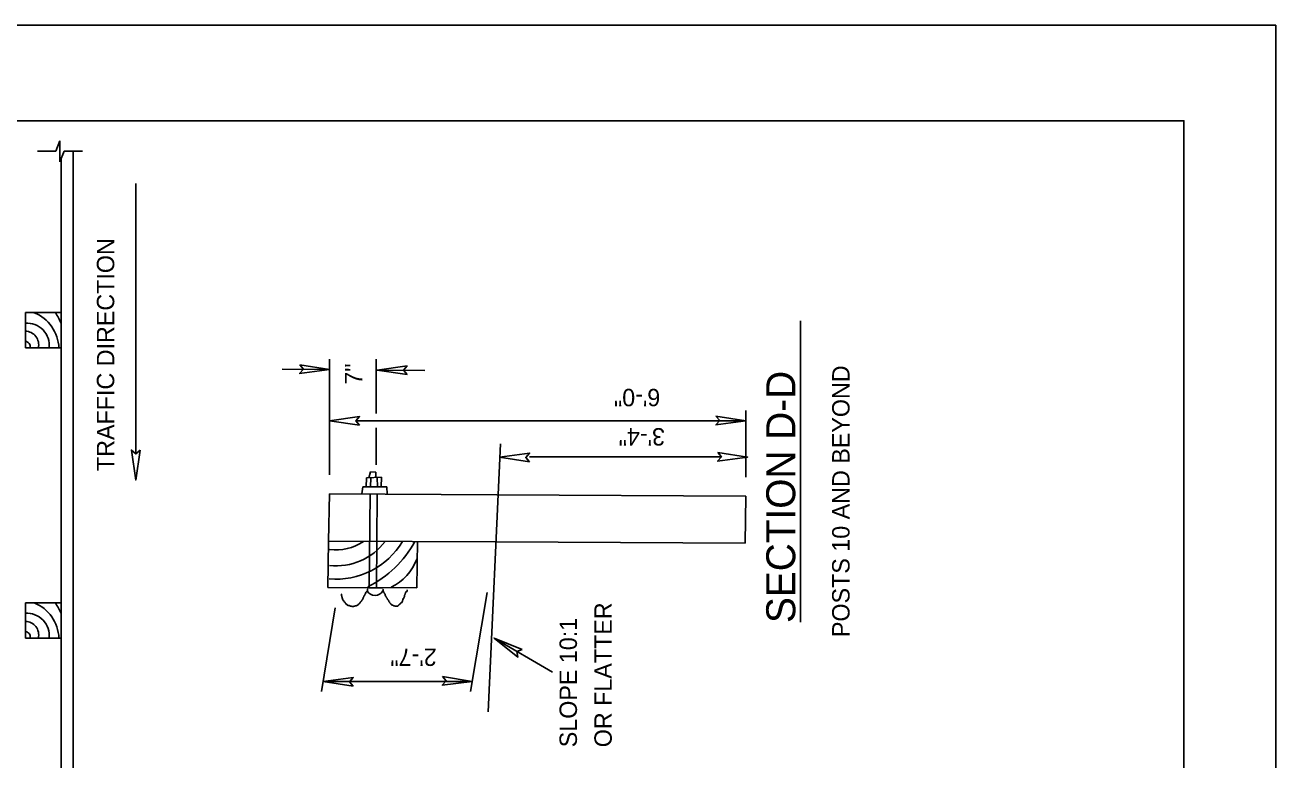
# Model space of a CAD drawing. Extents: x 12.2 to 54.5, y -7.8 to 16.1.
# Drawn here: x 50.224 to 54.534, y 0.687 to 3.22 of the extents above; entities that cross this region are included whole.
import ezdxf

# ---------------------------------------------------------------- set-up
doc = ezdxf.new("R2010")
doc.units = 0
for name, color, linetype in [('BORD-LINE', 7, 'Continuous'), ('DETL-DIMS', 7, 'Continuous'), ('DETL-LINE', 7, 'Continuous'), ('DETL-NOTE', 7, 'Continuous'), ('DETL-PATT', 7, 'Continuous'), ('DETL-TITL', 7, 'Continuous'), ('USER-BORD', 7, 'Continuous')]:
    doc.layers.add(name, color=color, linetype=linetype)

msp = doc.modelspace()

# ---------------------------------------------------------------- linework, layer by layer
at = {"layer": 'BORD-LINE'}
msp.add_lwpolyline([(46.8431, 2.8902), (54.2173, 2.8902), (54.2173, -7.4629), (46.8431, -7.4629)], close=True, dxfattribs=at)
at = {"layer": 'DETL-DIMS'}
for p, q in [((50.6056, 1.7422), (50.6056, 2.6735)), ((51.1095, 2.0345), (51.2734, 2.0332)), ((51.1699, 2.019), (51.183, 2.0339)), ((51.1699, 2.019), (51.2734, 2.0332)), ((51.1702, 2.0491), (51.2734, 2.0332)), ((51.1702, 2.0491), (51.183, 2.0339)), ((51.2734, 1.6698), (51.2734, 2.0682)), ((51.4335, 1.8814), (51.4335, 2.0682)), ((51.5405, 2.0455), (51.4371, 2.0312)), ((51.4371, 2.0312), (51.601, 2.03)), ((51.5402, 2.0154), (51.4371, 2.0312)), ((51.5405, 2.0455), (51.5275, 2.0305)), ((51.5402, 2.0154), (51.5275, 2.0305)), ((51.3768, 1.8706), (51.2734, 1.8564)), ((51.3765, 1.8405), (51.2734, 1.8564)), ((51.3768, 1.8706), (51.3638, 1.8556)), ((52.7079, 1.8564), (51.3638, 1.8556)), ((51.3765, 1.8405), (51.3638, 1.8556)), ((52.6045, 1.842), (52.6176, 1.857)), ((52.6045, 1.842), (52.7079, 1.8564)), ((52.6047, 1.8721), (52.7079, 1.8564)), ((52.6047, 1.8721), (52.6176, 1.857)), ((52.708, 1.8914), (52.7075, 1.6615)), ((51.4335, 1.7049), (51.4335, 1.8314)), ((50.5905, 1.7551), (50.6056, 1.6518)), ((50.5905, 1.7551), (50.6056, 1.7422)), ((50.6207, 1.7551), (50.6056, 1.6518)), ((50.6207, 1.7551), (50.6056, 1.7422)), ((51.9624, 1.7446), (51.859, 1.7308)), ((51.9621, 1.7145), (51.859, 1.7308)), ((51.9624, 1.7446), (51.9493, 1.7297)), ((51.9621, 1.7145), (51.9493, 1.7297)), ((52.6232, 1.7319), (51.9622, 1.7325)), ((52.6102, 1.7169), (52.6232, 1.7319)), ((52.6102, 1.7169), (52.7137, 1.7308)), ((52.6105, 1.7471), (52.7137, 1.7308)), ((52.6105, 1.7471), (52.6232, 1.7319)), ((51.8163, 1.2645), (51.7592, 0.9235)), ((51.2927, 1.212), (51.2456, 0.9234)), ((51.922, 1.0419), (51.8403, 1.107)), ((51.9371, 1.0679), (51.8403, 1.107)), ((52.0409, 0.9899), (51.8403, 1.107)), ((51.9371, 1.0679), (51.9184, 1.0614)), ((51.922, 1.0419), (51.9184, 1.0614)), ((51.3547, 0.9713), (51.2512, 0.958)), ((51.3542, 0.9412), (51.2512, 0.958)), ((51.765, 0.958), (51.2512, 0.958)), ((51.3547, 0.9713), (51.3415, 0.9565)), ((51.3542, 0.9412), (51.3415, 0.9565)), ((51.6616, 0.9447), (51.6747, 0.9595)), ((51.6616, 0.9447), (51.765, 0.958)), ((51.662, 0.9748), (51.765, 0.958)), ((51.662, 0.9748), (51.6747, 0.9595))]:
    msp.add_line(p, q, dxfattribs=at)
for points in [[(51.1702, 2.0491), (51.2734, 2.0332), (51.1699, 2.019), (51.183, 2.0339)], [(51.5402, 2.0154), (51.4371, 2.0312), (51.5405, 2.0455), (51.5275, 2.0305)], [(51.3765, 1.8405), (51.2734, 1.8564), (51.3768, 1.8706), (51.3638, 1.8556)], [(52.6047, 1.8721), (52.7079, 1.8564), (52.6045, 1.842), (52.6176, 1.857)], [(50.6207, 1.7551), (50.6056, 1.6518), (50.5905, 1.7551), (50.6056, 1.7422)], [(51.9621, 1.7145), (51.859, 1.7308), (51.9624, 1.7446), (51.9493, 1.7297)], [(52.6105, 1.7471), (52.7137, 1.7308), (52.6102, 1.7169), (52.6232, 1.7319)], [(51.9371, 1.0679), (51.8403, 1.107), (51.922, 1.0419), (51.9184, 1.0614)], [(51.3542, 0.9412), (51.2512, 0.958), (51.3547, 0.9713), (51.3415, 0.9565)], [(51.662, 0.9748), (51.765, 0.958), (51.6616, 0.9447), (51.6747, 0.9595)]]:
    msp.add_lwpolyline(points, close=True, dxfattribs=at)
at = {"layer": 'DETL-LINE'}
for p, q in [((50.3296, 2.7851), (50.3441, 2.821)), ((50.3441, 2.821), (50.3441, 2.7492)), ((50.2663, 2.7851), (50.3235, 2.7851)), ((50.3296, 2.7851), (50.3235, 2.7851)), ((50.3441, 2.7492), (50.3586, 2.7851)), ((50.3485, -5.332), (50.3485, 2.7601)), ((50.3647, 2.7851), (50.3586, 2.7851)), ((50.3647, 2.7851), (50.4219, 2.7851)), ((50.3897, 2.7851), (50.3836, 2.7851)), ((50.3897, -5.332), (50.3897, 2.7851)), ((50.225, 2.1071), (50.225, 2.229)), ((50.225, 2.229), (50.3485, 2.229)), ((50.3485, 2.1071), (50.3485, 2.229)), ((50.3485, 2.168), (50.3485, 2.168)), ((50.3485, 2.168), (50.3485, 2.168)), ((50.225, 2.1071), (50.3485, 2.1071)), ((51.8616, 1.7768), (51.8195, 0.8528)), ((51.3991, 1.6289), (51.4, 1.6592)), ((51.4, 1.6592), (51.4523, 1.6615)), ((51.4086, 1.6596), (51.4137, 1.6803)), ((51.4137, 1.6803), (51.4327, 1.6795)), ((51.4148, 1.6599), (51.4144, 1.6289)), ((51.4327, 1.6795), (51.4328, 1.6606)), ((51.4375, 1.6609), (51.4378, 1.6288)), ((51.4523, 1.6615), (51.451, 1.6287)), ((51.2734, 1.6048), (51.2696, 1.441)), ((51.8492, 1.6014), (51.2734, 1.6048)), ((51.3841, 1.6041), (51.3873, 1.629)), ((51.3873, 1.629), (51.4707, 1.6286)), ((51.4099, 1.2815), (51.4125, 1.604)), ((51.4377, 1.6038), (51.4351, 1.2814)), ((51.4707, 1.6286), (51.4712, 1.6036)), ((51.8492, 1.6014), (52.7075, 1.5965)), ((52.7056, 1.4342), (52.7075, 1.5965)), ((51.2676, 1.2819), (51.2696, 1.441)), ((51.2696, 1.441), (51.8458, 1.439)), ((51.5763, 1.4416), (51.5734, 1.281)), ((51.8458, 1.439), (52.7056, 1.4342)), ((52.7056, 1.4342), (52.7056, 1.4342)), ((51.5734, 1.281), (51.2676, 1.2819)), ((51.4042, 1.2804), (51.4567, 1.2804)), ((50.225, 1.1071), (50.225, 1.229)), ((50.225, 1.229), (50.3485, 1.229)), ((50.3485, 1.1071), (50.3485, 1.229)), ((50.3485, 1.168), (50.3485, 1.168)), ((50.225, 1.1071), (50.3485, 1.1071))]:
    msp.add_line(p, q, dxfattribs=at)
msp.add_arc((51.4299, 1.2857), 0.0313, 209.9079, 329.8397, dxfattribs=at)
for points in [[(51.3153, 1.259), (51.3144, 1.2575), (51.3144, 1.2547), (51.3148, 1.2532), (51.3158, 1.2514), (51.3158, 1.248), (51.3163, 1.248), (51.3163, 1.2466), (51.3173, 1.2437), (51.3178, 1.2437), (51.3178, 1.2419), (51.3207, 1.2375), (51.3211, 1.2375), (51.3211, 1.2362), (51.3221, 1.2347), (51.3226, 1.2352), (51.3231, 1.2332), (51.3241, 1.2332), (51.3241, 1.2319), (51.325, 1.2304), (51.3269, 1.23), (51.3264, 1.229), (51.3279, 1.2275), (51.3289, 1.2271), (51.3292, 1.2262), (51.3297, 1.2247), (51.3307, 1.2238), (51.3327, 1.2233), (51.3341, 1.2228), (51.3345, 1.2219), (51.3346, 1.2204), (51.3355, 1.2204), (51.337, 1.2195), (51.3393, 1.219), (51.3412, 1.219), (51.3437, 1.2176), (51.345, 1.2176), (51.3465, 1.2176), (51.3493, 1.2168), (51.3498, 1.2163), (51.3546, 1.2163), (51.3565, 1.2163), (51.358, 1.2173), (51.3588, 1.2177), (51.3593, 1.2173), (51.3617, 1.2182), (51.3632, 1.2182), (51.3646, 1.2182), (51.366, 1.2187), (51.3665, 1.2192), (51.3675, 1.2187), (51.3688, 1.2202), (51.3708, 1.2212), (51.3732, 1.2236), (51.374, 1.224), (51.3745, 1.225), (51.3764, 1.227), (51.3769, 1.227), (51.3774, 1.2283), (51.3783, 1.2288), (51.3783, 1.2298), (51.3798, 1.2313), (51.3807, 1.2327), (51.3817, 1.2336), (51.3831, 1.2346), (51.3835, 1.2361), (51.3845, 1.2366), (51.3845, 1.2374), (51.3854, 1.2389), (51.3864, 1.2394), (51.3873, 1.2422), (51.3878, 1.2427), (51.3887, 1.2447), (51.3887, 1.2461), (51.3892, 1.2462), (51.3896, 1.248), (51.3906, 1.248), (51.3911, 1.25), (51.3925, 1.2528), (51.3934, 1.2543), (51.3944, 1.2552), (51.3949, 1.2562), (51.3948, 1.2576), (51.3963, 1.2595), (51.3968, 1.261), (51.4005, 1.2667), (51.4015, 1.2682), (51.402, 1.2686), (51.4043, 1.2739), (51.4043, 1.2759), (51.4048, 1.2772)], [(51.4564, 1.2758), (51.4578, 1.2715), (51.4578, 1.2695), (51.4583, 1.2686), (51.4588, 1.2676), (51.4603, 1.2663), (51.4603, 1.2648), (51.4612, 1.2633), (51.4617, 1.2619), (51.4631, 1.2605), (51.4631, 1.2591), (51.4651, 1.2576), (51.4656, 1.2528), (51.4664, 1.2524), (51.467, 1.2515), (51.4675, 1.2501), (51.4684, 1.2481), (51.4704, 1.2463), (51.4717, 1.2424), (51.4727, 1.241), (51.4737, 1.241), (51.4742, 1.2386), (51.4752, 1.2376), (51.4762, 1.2372), (51.4775, 1.2343), (51.4785, 1.2324), (51.4795, 1.2315), (51.479, 1.231), (51.4823, 1.2276), (51.4833, 1.2258), (51.4848, 1.2243), (51.4852, 1.2243), (51.4871, 1.2225), (51.4896, 1.2206), (51.491, 1.2206), (51.4933, 1.2191), (51.4948, 1.2182), (51.4967, 1.2182), (51.4976, 1.2177), (51.5019, 1.2177), (51.5044, 1.2174), (51.5062, 1.2174), (51.5081, 1.2178), (51.5096, 1.2188), (51.5101, 1.2198), (51.5109, 1.2202), (51.5114, 1.2212), (51.5124, 1.2222), (51.5138, 1.2231), (51.5153, 1.224), (51.5161, 1.2245), (51.5161, 1.226), (51.5171, 1.2265), (51.5176, 1.2274), (51.5186, 1.2284), (51.52, 1.2284), (51.5233, 1.2327), (51.5238, 1.2346), (51.5247, 1.2342), (51.5247, 1.2361), (51.5252, 1.2375), (51.5256, 1.2404), (51.527, 1.2404), (51.5261, 1.2419), (51.5266, 1.2432), (51.5285, 1.2437), (51.5294, 1.2457), (51.5313, 1.25), (51.5313, 1.2514), (51.5317, 1.2533), (51.5317, 1.2552), (51.5327, 1.2567), (51.5332, 1.2581), (51.5332, 1.2595), (51.5346, 1.2619), (51.535, 1.2638), (51.5359, 1.2653), (51.5364, 1.2672), (51.5374, 1.2672), (51.5407, 1.2696), (51.5406, 1.2734)]]:
    msp.add_spline(points, degree=3, dxfattribs=at)
at = {"layer": 'DETL-PATT'}
for centre, radius, start, end in [((51.295, 1.5775), 0.2674, 265.0433, 329.1127), ((51.2938, 1.5806), 0.1698, 263.0032, 304.4788), ((51.2963, 1.5673), 0.2109, 263.6878, 323.0107), ((51.2379, 1.618), 0.3738, 296.6169, 331.5711), ((51.408, 1.4415), 0.177, 296.0413, 339.5471)]:
    msp.add_arc(centre, radius, start, end, dxfattribs=at)
for centre, major_axis, start_param, end_param in [((50.205, 2.1017), (0, 0.137), 4.750897, 5.899278), ((50.0724, 2.0628), (0, 0.3071), 5.144981, 5.283467), ((50.2309, 2.1156), (0, 0.0772), 4.600695, 6.361038), ((50.2243, 2.1177), (0, 0.0472), 4.485117, 6.270221), ((50.2243, 2.1121), (0, 0.0174), 4.485117, 6.270221), ((50.205, 1.1017), (0, 0.137), 4.750897, 5.899278), ((50.0724, 1.0628), (0, 0.3071), 5.144981, 5.283467), ((50.2309, 1.1156), (0, 0.0772), 4.600695, 6.361038), ((50.2243, 1.1177), (0, 0.0472), 4.485117, 6.270221), ((50.2243, 1.1121), (0, 0.0174), 4.485117, 6.270221)]:
    msp.add_ellipse(centre, major_axis=major_axis, ratio=0.989796, start_param=start_param, end_param=end_param, dxfattribs=at)
at = {"layer": 'DETL-TITL'}
msp.add_line((52.8964, 1.1622), (52.8964, 2.2011), dxfattribs=at)
at = {"layer": 'USER-BORD'}
msp.add_lwpolyline([(54.5342, 3.2202), (46.0342, 3.2202), (46.0342, -7.7798), (54.5342, -7.7798)], close=True, dxfattribs=at)

# ---------------------------------------------------------------- texts
at = {"layer": 'DETL-NOTE'}
for s, rotation, p in [('TRAFFIC DIRECTION', 90, (50.5313, 1.683)), ('7"', 90, (51.3859, 1.9806)), ('POSTS 10 AND BEYOND', 90, (53.0649, 1.1107)), ('6\'-0"', 180, (52.4128, 1.9663)), ('3\'-4"', 180, (52.429, 1.8309)), ('OR FLATTER', 90, (52.2456, 0.731)), ('SLOPE 10:1', 90, (52.1256, 0.731)), ('2\'-7"', 180, (51.6423, 1.0713))]:
    msp.add_text(s, height=0.06, rotation=rotation, dxfattribs=at).set_placement(p)
at = {"layer": 'DETL-TITL'}
msp.add_text('SECTION D-D', height=0.1, rotation=90, dxfattribs=at).set_placement((52.8779, 1.1592))

doc.saveas('drawing.dxf')
